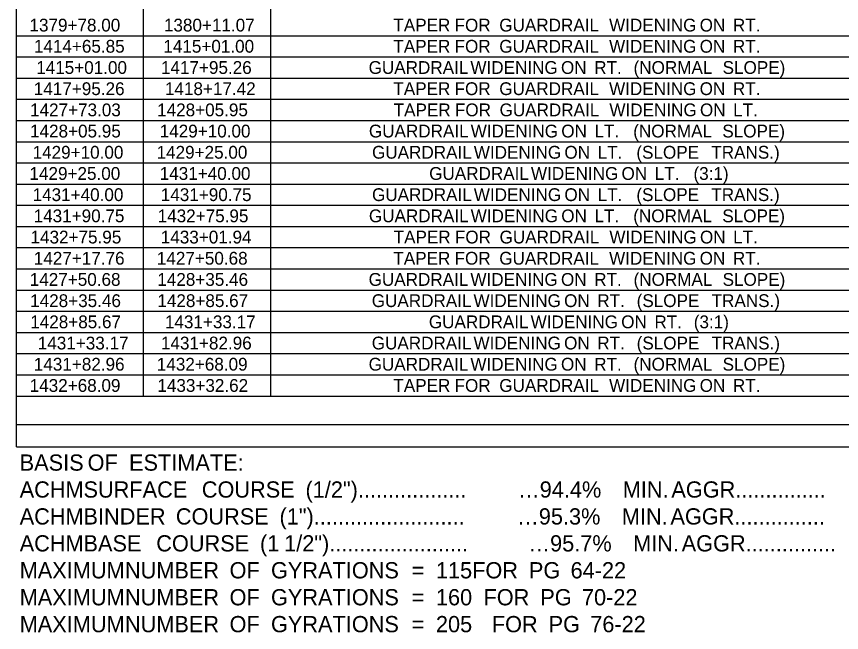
# Model space of a CAD drawing. Extents: x 1226590 to 1228573, y 151304 to 154224.
# Drawn here: x 1226590.3 to 1226844.3, y 151427.8 to 151617.4 of the extents above; entities that cross this region are included whole.
import ezdxf

# ---------------------------------------------------------------- set-up
doc = ezdxf.new("R2010")
doc.units = 0
doc.layers.add('R_Dimension', color=7, linetype='Continuous')

msp = doc.modelspace()

# ---------------------------------------------------------------- linework, layer by layer
at = {"layer": 'R_Dimension'}
for p, q in [((1226590.27, 151484.92), (1226590.27, 152182.03)), ((1226629.41, 151500.6), (1226629.41, 151957.19)), ((1226668.54, 151500.6), (1226668.54, 151957.19)), ((1226590.27, 151611.49), (1228150.73, 151611.49)), ((1226590.27, 151604.96), (1228150.73, 151604.96)), ((1226590.27, 151598.44), (1228150.73, 151598.44)), ((1226590.27, 151591.92), (1228150.73, 151591.92)), ((1226590.27, 151585.4), (1228150.73, 151585.4)), ((1226590.27, 151578.87), (1228150.73, 151578.87)), ((1226590.27, 151572.35), (1228150.73, 151572.35)), ((1226590.27, 151565.83), (1228150.73, 151565.83)), ((1226590.27, 151559.3), (1228150.73, 151559.3)), ((1226590.27, 151552.78), (1228150.73, 151552.78)), ((1226590.27, 151546.26), (1228150.73, 151546.26)), ((1226590.27, 151539.74), (1228150.73, 151539.74)), ((1226590.27, 151533.21), (1228150.73, 151533.21)), ((1226590.27, 151526.69), (1228150.73, 151526.69)), ((1226590.27, 151520.17), (1228150.73, 151520.17)), ((1226590.27, 151513.65), (1228150.73, 151513.65)), ((1226590.27, 151507.12), (1228150.73, 151507.12)), ((1226590.27, 151500.6), (1228150.73, 151500.6)), ((1226590.27, 151491.83), (1228150.75, 151491.83)), ((1226590.27, 151484.92), (1228150.75, 151484.92))]:
    msp.add_line(p, q, dxfattribs=at)

# ---------------------------------------------------------------- texts
for s, height, p in [('1379+78.00', 3.935, (1226594.27, 151612.78)), ('1380+11.07', 3.935, (1226635.65, 151612.78)), ('TAPER', 3.935, (1226706.3, 151612.78)), (' FOR', 3.935, (1226723.68, 151612.78)), (' GUARDRAIL', 3.935, (1226737.44, 151612.78)), (' WIDENING', 3.935, (1226771.25, 151612.78)), (' ON', 3.935, (1226799.14, 151612.78)), (' RT.', 3.935, (1226809.36, 151612.78)), ('1414+65.85', 3.935, (1226595.62, 151606.26)), ('1415+01.00', 3.935, (1226635.48, 151606.26)), ('TAPER', 3.935, (1226706.3, 151606.26)), (' FOR', 3.935, (1226723.68, 151606.26)), (' GUARDRAIL', 3.935, (1226737.44, 151606.26)), (' WIDENING', 3.935, (1226771.25, 151606.26)), (' ON', 3.935, (1226799.14, 151606.26)), (' RT.', 3.935, (1226809.36, 151606.26)), ('1415+01.00', 3.935, (1226596.34, 151599.73)), ('1417+95.26', 3.935, (1226634.74, 151599.73)), ('GUARDRAIL', 3.935, (1226698.68, 151599.73)), (' WIDENING', 3.935, (1226728.55, 151599.73)), (' ON', 3.935, (1226756.44, 151599.73)), (' RT.', 3.935, (1226766.66, 151599.73)), (' (NORMAL', 3.935, (1226778.78, 151599.73)), (' SLOPE)', 3.935, (1226806.2, 151599.73)), ('1417+95.26', 3.935, (1226595.6, 151593.21)), ('1418+17.42', 3.935, (1226635.96, 151593.21)), ('TAPER', 3.935, (1226706.3, 151593.21)), (' FOR', 3.935, (1226723.68, 151593.21)), (' GUARDRAIL', 3.935, (1226737.44, 151593.21)), (' WIDENING', 3.935, (1226771.25, 151593.21)), (' ON', 3.935, (1226799.14, 151593.21)), (' RT.', 3.935, (1226809.36, 151593.21)), ('1427+73.03', 3.935, (1226594.44, 151586.69)), ('1428+05.95', 3.935, (1226633.57, 151586.69)), ('TAPER', 3.935, (1226706.39, 151586.69)), (' FOR', 3.935, (1226723.78, 151586.69)), (' GUARDRAIL', 3.935, (1226737.53, 151586.69)), (' WIDENING', 3.935, (1226771.34, 151586.69)), (' ON', 3.935, (1226799.23, 151586.69)), (' LT.', 3.935, (1226809.45, 151586.69)), (' (NORMAL', 3.935, (1226778.68, 151580.17)), (' SLOPE)', 3.935, (1226806.11, 151580.17)), ('1428+05.95', 3.935, (1226594.44, 151580.17)), ('1429+10.00', 3.935, (1226634.36, 151580.17)), ('GUARDRAIL', 3.935, (1226698.77, 151580.17)), (' WIDENING', 3.935, (1226728.64, 151580.17)), (' ON', 3.935, (1226756.53, 151580.17)), (' LT.', 3.935, (1226766.76, 151580.17)), ('1429+10.00', 3.935, (1226595.23, 151573.64)), ('1429+25.00', 3.935, (1226633.4, 151573.64)), ('GUARDRAIL', 3.935, (1226699.73, 151573.64)), (' WIDENING', 3.935, (1226729.6, 151573.64)), (' ON', 3.935, (1226757.49, 151573.64)), (' LT.', 3.935, (1226767.72, 151573.64)), (' (SLOPE', 3.935, (1226779.65, 151573.64)), (' TRANS.)', 3.935, (1226802.73, 151573.64)), ('1429+25.00', 3.935, (1226594.27, 151567.12)), ('1431+40.00', 3.935, (1226634.36, 151567.12)), ('GUARDRAIL', 3.935, (1226717.32, 151567.12)), (' WIDENING', 3.935, (1226747.19, 151567.12)), (' ON', 3.935, (1226775.07, 151567.12)), (' LT.', 3.935, (1226785.3, 151567.12)), (' (3:1)', 3.935, (1226797.23, 151567.12)), ('1431+40.00', 3.935, (1226595.23, 151560.6)), ('1431+90.75', 3.935, (1226634.69, 151560.6)), ('GUARDRAIL', 3.935, (1226699.73, 151560.6)), (' WIDENING', 3.935, (1226729.6, 151560.6)), (' ON', 3.935, (1226757.49, 151560.6)), (' LT.', 3.935, (1226767.72, 151560.6)), (' (SLOPE', 3.935, (1226779.65, 151560.6)), (' TRANS.)', 3.935, (1226802.73, 151560.6)), ('1431+90.75', 3.935, (1226595.55, 151554.08)), ('1432+75.95', 3.935, (1226633.73, 151554.08)), ('GUARDRAIL', 3.935, (1226698.77, 151554.08)), (' WIDENING', 3.935, (1226728.64, 151554.08)), (' ON', 3.935, (1226756.53, 151554.08)), (' LT.', 3.935, (1226766.76, 151554.08)), (' (NORMAL', 3.935, (1226778.68, 151554.08)), (' SLOPE)', 3.935, (1226806.11, 151554.08)), ('1432+75.95', 3.935, (1226594.59, 151547.55)), ('1433+01.94', 3.935, (1226634.69, 151547.55)), ('TAPER', 3.935, (1226706.39, 151547.55)), (' FOR', 3.935, (1226723.78, 151547.55)), (' GUARDRAIL', 3.935, (1226737.53, 151547.55)), (' WIDENING', 3.935, (1226771.34, 151547.55)), (' ON', 3.935, (1226799.23, 151547.55)), (' LT.', 3.935, (1226809.45, 151547.55)), ('1427+17.76', 3.935, (1226595.6, 151541.03)), ('1427+50.68', 3.935, (1226633.48, 151541.03)), ('TAPER', 3.935, (1226706.3, 151541.03)), (' FOR', 3.935, (1226723.68, 151541.03)), (' GUARDRAIL', 3.935, (1226737.44, 151541.03)), (' WIDENING', 3.935, (1226771.25, 151541.03)), (' ON', 3.935, (1226799.14, 151541.03)), (' RT.', 3.935, (1226809.36, 151541.03)), (' (NORMAL', 3.935, (1226778.78, 151534.51)), (' SLOPE)', 3.935, (1226806.2, 151534.51)), ('1427+50.68', 3.935, (1226594.35, 151534.51)), ('1428+35.46', 3.935, (1226633.62, 151534.51)), ('GUARDRAIL', 3.935, (1226698.68, 151534.51)), (' WIDENING', 3.935, (1226728.55, 151534.51)), (' ON', 3.935, (1226756.44, 151534.51)), (' RT.', 3.935, (1226766.66, 151534.51)), ('1428+35.46', 3.935, (1226594.48, 151527.98)), ('1428+85.67', 3.935, (1226633.64, 151527.98)), ('GUARDRAIL', 3.935, (1226699.64, 151527.98)), (' WIDENING', 3.935, (1226729.51, 151527.98)), (' ON', 3.935, (1226757.4, 151527.98)), (' RT.', 3.935, (1226767.62, 151527.98)), (' (SLOPE', 3.935, (1226779.74, 151527.98)), (' TRANS.)', 3.935, (1226802.82, 151527.98)), ('1428+85.67', 3.935, (1226594.5, 151521.46)), ('1431+33.17', 3.935, (1226635.96, 151521.46)), ('GUARDRAIL', 3.935, (1226717.22, 151521.46)), (' WIDENING', 3.935, (1226747.09, 151521.46)), (' ON', 3.935, (1226774.98, 151521.46)), (' RT.', 3.935, (1226785.21, 151521.46)), (' (3:1)', 3.935, (1226797.32, 151521.46)), ('1431+33.17', 3.935, (1226596.82, 151514.94)), ('1431+82.96', 3.935, (1226634.74, 151514.94)), ('GUARDRAIL', 3.935, (1226699.64, 151514.94)), (' WIDENING', 3.935, (1226729.51, 151514.94)), (' ON', 3.935, (1226757.4, 151514.94)), (' RT.', 3.935, (1226767.62, 151514.94)), (' (SLOPE', 3.935, (1226779.74, 151514.94)), (' TRANS.)', 3.935, (1226802.82, 151514.94)), ('1431+82.96', 3.935, (1226595.6, 151508.42)), ('1432+68.09', 3.935, (1226633.47, 151508.42)), ('GUARDRAIL', 3.935, (1226698.68, 151508.42)), (' WIDENING', 3.935, (1226728.55, 151508.42)), (' ON', 3.935, (1226756.44, 151508.42)), (' RT.', 3.935, (1226766.66, 151508.42)), (' (NORMAL', 3.935, (1226778.78, 151508.42)), (' SLOPE)', 3.935, (1226806.2, 151508.42)), ('1432+68.09', 3.935, (1226594.33, 151501.89)), ('1433+32.62', 3.935, (1226633.64, 151501.89)), ('TAPER', 3.935, (1226706.3, 151501.89)), (' FOR', 3.935, (1226723.68, 151501.89)), (' GUARDRAIL', 3.935, (1226737.44, 151501.89)), (' WIDENING', 3.935, (1226771.25, 151501.89)), (' ON', 3.935, (1226799.14, 151501.89)), (' RT.', 3.935, (1226809.36, 151501.89)), ('BASIS', 5, (1226591.25, 151477.63)), (' OF', 5, (1226610.3, 151477.63)), (' ESTIMATE:', 5, (1226623.06, 151477.63)), ('ACHM', 5, (1226591.25, 151469.34)), (' SURFACE', 5, (1226609.04, 151469.34)), (' COURSE', 5, (1226645.46, 151469.34)), (' (1/2")..................', 5, (1226677.39, 151469.34)), ('…94.4% ', 5, (1226744.67, 151469.34)), ('MIN. ', 5, (1226776.91, 151469.34)), ('AGGR...............', 5, (1226791.88, 151469.34)), ('ACHM', 5, (1226591.25, 151461.06)), (' BINDER', 5, (1226609.04, 151461.06)), (' COURSE', 5, (1226637.47, 151461.06)), (' (1").........................', 5, (1226669.39, 151461.06)), ('…95.3% ', 5, (1226744.39, 151461.06)), ('MIN. ', 5, (1226776.64, 151461.06)), ('AGGR...............', 5, (1226791.6, 151461.06)), ('ACHM', 5, (1226591.25, 151452.77)), (' BASE', 5, (1226609.04, 151452.77)), (' COURSE', 5, (1226631.44, 151452.77)), (' (1', 5, (1226663.37, 151452.77)), (' 1/2").......................', 5, (1226670.81, 151452.77)), ('…95.7% ', 5, (1226747.86, 151452.77)), ('MIN. ', 5, (1226780.1, 151452.77)), ('AGGR...............', 5, (1226795.06, 151452.77)), ('MAXIMUM', 5, (1226591.25, 151444.48)), (' NUMBER', 5, (1226621.8, 151444.48)), (' OF', 5, (1226654, 151444.48)), (' GYRATIONS', 5, (1226666.76, 151444.48)), (' =', 5, (1226710.1, 151444.48)), (' 115', 5, (1226717.54, 151444.48)), (' FOR', 5, (1226728.69, 151444.48)), (' PG', 5, (1226746.17, 151444.48)), (' 64-22', 5, (1226759, 151444.48)), ('MAXIMUM', 5, (1226591.25, 151436.19)), (' NUMBER', 5, (1226621.8, 151436.19)), (' OF', 5, (1226654, 151436.19)), (' GYRATIONS', 5, (1226666.76, 151436.19)), (' =', 5, (1226710.1, 151436.19)), (' 160', 5, (1226717.54, 151436.19)), (' FOR', 5, (1226732.19, 151436.19)), (' PG', 5, (1226749.67, 151436.19)), (' 70-22', 5, (1226762.5, 151436.19)), ('MAXIMUM', 5, (1226591.25, 151427.91)), (' NUMBER', 5, (1226621.8, 151427.91)), (' OF', 5, (1226654, 151427.91)), (' GYRATIONS', 5, (1226666.76, 151427.91)), (' 205', 5, (1226717.54, 151427.91)), (' FOR', 5, (1226734.75, 151427.91)), (' PG', 5, (1226752.23, 151427.91)), (' 76-22', 5, (1226765.06, 151427.91)), (' =', 5, (1226710.1, 151427.91))]:
    msp.add_text(s, height=height, dxfattribs=at).set_placement(p)

doc.saveas('drawing.dxf')
